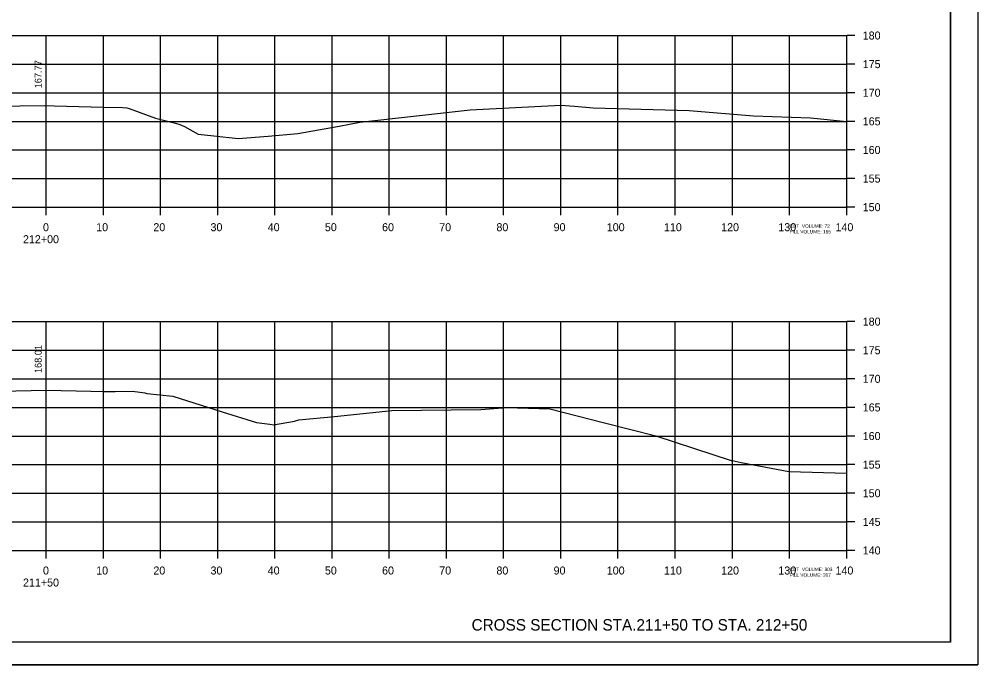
# Model space of a CAD drawing. Extents: x 1368503 to 1373085, y 379840 to 381833.
# Drawn here: x 1368668.3 to 1368836, y 380979.4 to 381092.2 of the extents above; entities that cross this region are included whole.
import ezdxf

# ---------------------------------------------------------------- set-up
doc = ezdxf.new("R2010")
doc.units = 0
for name, color, linetype in [('S_BRIDGE', 7, 'Continuous'), ('S_EDGE_PAVEMENT', 7, 'Continuous'), ('S_MISC_BOUNDARY', 7, 'Continuous'), ('S_PHOTO_CENTERS', 7, 'Continuous'), ('S_PHOTO_NOTES', 7, 'Continuous'), ('S_TRAILS', 7, 'Continuous'), ('S_TRAILS_ANNOT', 7, 'Continuous'), ('S_TREE', 7, 'Continuous')]:
    doc.layers.add(name, color=color, linetype=linetype)

msp = doc.modelspace()

# ---------------------------------------------------------------- linework, layer by layer
at = {"layer": 'S_BRIDGE'}
for q in [(1368831.24, 381188.84), (1368515.06, 380983.38)]:
    msp.add_line((1368831.24, 380983.38), q, dxfattribs=at)
at = {"layer": 'S_EDGE_PAVEMENT'}
for p, q in [((1368813.06, 381059.38), (1368813.06, 381089.38)), ((1368814.46, 381089.38), (1368813.06, 381089.38)), ((1368814.46, 381084.38), (1368813.06, 381084.38)), ((1368814.46, 381079.38), (1368813.06, 381079.38)), ((1368814.46, 381074.38), (1368813.06, 381074.38)), ((1368814.46, 381069.38), (1368813.06, 381069.38)), ((1368814.46, 381064.38), (1368813.06, 381064.38)), ((1368533.06, 381059.38), (1368813.06, 381059.38)), ((1368673.06, 381057.98), (1368673.06, 381059.38)), ((1368683.06, 381057.98), (1368683.06, 381059.38)), ((1368693.06, 381057.98), (1368693.06, 381059.38)), ((1368703.06, 381057.98), (1368703.06, 381059.38)), ((1368713.06, 381057.98), (1368713.06, 381059.38)), ((1368723.06, 381057.98), (1368723.06, 381059.38)), ((1368733.06, 381057.98), (1368733.06, 381059.38)), ((1368743.06, 381057.98), (1368743.06, 381059.38)), ((1368753.06, 381057.98), (1368753.06, 381059.38)), ((1368763.06, 381057.98), (1368763.06, 381059.38)), ((1368773.06, 381057.98), (1368773.06, 381059.38)), ((1368783.06, 381057.98), (1368783.06, 381059.38)), ((1368793.06, 381057.98), (1368793.06, 381059.38)), ((1368803.06, 381057.98), (1368803.06, 381059.38)), ((1368813.06, 381057.98), (1368813.06, 381059.38)), ((1368814.46, 381059.38), (1368813.06, 381059.38)), ((1368813.06, 380999.38), (1368813.06, 381039.38)), ((1368814.46, 381039.38), (1368813.06, 381039.38)), ((1368814.46, 381034.38), (1368813.06, 381034.38)), ((1368814.46, 381029.38), (1368813.06, 381029.38)), ((1368814.46, 381024.38), (1368813.06, 381024.38)), ((1368814.46, 381019.38), (1368813.06, 381019.38)), ((1368814.46, 381014.38), (1368813.06, 381014.38)), ((1368814.46, 381009.38), (1368813.06, 381009.38)), ((1368814.46, 381004.38), (1368813.06, 381004.38)), ((1368533.06, 380999.38), (1368813.06, 380999.38)), ((1368673.06, 380997.98), (1368673.06, 380999.38)), ((1368683.06, 380997.98), (1368683.06, 380999.38)), ((1368693.06, 380997.98), (1368693.06, 380999.38)), ((1368703.06, 380997.98), (1368703.06, 380999.38)), ((1368713.06, 380997.98), (1368713.06, 380999.38)), ((1368723.06, 380997.98), (1368723.06, 380999.38)), ((1368733.06, 380997.98), (1368733.06, 380999.38)), ((1368743.06, 380997.98), (1368743.06, 380999.38)), ((1368753.06, 380997.98), (1368753.06, 380999.38)), ((1368763.06, 380997.98), (1368763.06, 380999.38)), ((1368773.06, 380997.98), (1368773.06, 380999.38)), ((1368783.06, 380997.98), (1368783.06, 380999.38)), ((1368793.06, 380997.98), (1368793.06, 380999.38)), ((1368803.06, 380997.98), (1368803.06, 380999.38)), ((1368813.06, 380997.98), (1368813.06, 380999.38)), ((1368814.46, 380999.38), (1368813.06, 380999.38))]:
    msp.add_line(p, q, dxfattribs=at)
at = {"layer": 'S_MISC_BOUNDARY'}
for points in [[(1368664.16, 381077.03), (1368672.72, 381077.15), (1368674.47, 381077.11), (1368683.1, 381076.88), (1368686.43, 381076.78), (1368687.14, 381076.76), (1368687.55, 381076.61), (1368692.19, 381074.96), (1368695.69, 381074.05), (1368696.45, 381073.8), (1368697.27, 381073.47), (1368699.63, 381072.16), (1368702.36, 381071.86), (1368706.65, 381071.37), (1368711.9, 381071.8), (1368717.09, 381072.24), (1368724.31, 381073.51), (1368727.92, 381074.26), (1368747.18, 381076.42), (1368763.08, 381077.22), (1368765.48, 381077.01), (1368768.72, 381076.74), (1368785.48, 381076.3), (1368796.76, 381075.37), (1368806.73, 381074.98), (1368813.06, 381074.35)], [(1368665.05, 381027.21), (1368673.12, 381027.39), (1368680.85, 381027.2), (1368683.12, 381027.14), (1368685.11, 381027.18), (1368688.17, 381027.2), (1368690.31, 381026.95), (1368690.66, 381026.79), (1368695.19, 381026.32), (1368703.83, 381023.6), (1368709.86, 381021.73), (1368712.19, 381021.44), (1368712.8, 381021.36), (1368716.51, 381021.99), (1368717.25, 381022.19), (1368723.48, 381022.82), (1368733.52, 381023.83), (1368749.06, 381023.99), (1368753.6, 381024.38), (1368761.16, 381024.12), (1368770.48, 381021.75), (1368779.68, 381019.41), (1368792.86, 381015.08), (1368792.87, 381015.08), (1368793.01, 381015.08), (1368794.58, 381014.78), (1368802.94, 381013.19), (1368813.06, 381012.89)]]:
    msp.add_lwpolyline(points, dxfattribs=at)
at = {"layer": 'S_PHOTO_CENTERS'}
for p, q in [((1368533.06, 381089.38), (1368813.06, 381089.38)), ((1368673.06, 381059.38), (1368673.06, 381089.38)), ((1368683.06, 381059.38), (1368683.06, 381089.38)), ((1368693.06, 381059.38), (1368693.06, 381089.38)), ((1368703.06, 381059.38), (1368703.06, 381089.38)), ((1368713.06, 381059.38), (1368713.06, 381089.38)), ((1368723.06, 381059.38), (1368723.06, 381089.38)), ((1368733.06, 381059.38), (1368733.06, 381089.38)), ((1368743.06, 381059.38), (1368743.06, 381089.38)), ((1368753.06, 381059.38), (1368753.06, 381089.38)), ((1368763.06, 381059.38), (1368763.06, 381089.38)), ((1368773.06, 381059.38), (1368773.06, 381089.38)), ((1368783.06, 381059.38), (1368783.06, 381089.38)), ((1368793.06, 381059.38), (1368793.06, 381089.38)), ((1368803.06, 381059.38), (1368803.06, 381089.38)), ((1368813.06, 381059.38), (1368813.06, 381089.38)), ((1368533.06, 381084.38), (1368813.06, 381084.38)), ((1368533.06, 381079.38), (1368813.06, 381079.38)), ((1368533.06, 381074.38), (1368813.06, 381074.38)), ((1368533.06, 381069.38), (1368813.06, 381069.38)), ((1368533.06, 381064.38), (1368813.06, 381064.38)), ((1368533.06, 381059.38), (1368813.06, 381059.38)), ((1368533.06, 381039.38), (1368813.06, 381039.38)), ((1368673.06, 380999.38), (1368673.06, 381039.38)), ((1368683.06, 380999.38), (1368683.06, 381039.38)), ((1368693.06, 380999.38), (1368693.06, 381039.38)), ((1368703.06, 380999.38), (1368703.06, 381039.38)), ((1368713.06, 380999.38), (1368713.06, 381039.38)), ((1368723.06, 380999.38), (1368723.06, 381039.38)), ((1368733.06, 380999.38), (1368733.06, 381039.38)), ((1368743.06, 380999.38), (1368743.06, 381039.38)), ((1368753.06, 380999.38), (1368753.06, 381039.38)), ((1368763.06, 380999.38), (1368763.06, 381039.38)), ((1368773.06, 380999.38), (1368773.06, 381039.38)), ((1368783.06, 380999.38), (1368783.06, 381039.38)), ((1368793.06, 380999.38), (1368793.06, 381039.38)), ((1368803.06, 380999.38), (1368803.06, 381039.38)), ((1368813.06, 380999.38), (1368813.06, 381039.38)), ((1368533.06, 381034.38), (1368813.06, 381034.38)), ((1368533.06, 381029.38), (1368813.06, 381029.38)), ((1368533.06, 381024.38), (1368813.06, 381024.38)), ((1368533.06, 381019.38), (1368813.06, 381019.38)), ((1368533.06, 381014.38), (1368813.06, 381014.38)), ((1368533.06, 381009.38), (1368813.06, 381009.38)), ((1368533.06, 381004.38), (1368813.06, 381004.38)), ((1368533.06, 380999.38), (1368813.06, 380999.38))]:
    msp.add_line(p, q, dxfattribs=at)
at = {"layer": 'S_PHOTO_NOTES'}
msp.add_line((1368502.66, 380979.4), (1368835.99, 380979.4), dxfattribs=at)
for points in [[(1368502.65, 381192.73), (1368835.99, 381192.73), (1368835.99, 380979.4), (1368502.65, 380979.4)], [(1368748.98, 381188.84), (1368748.98, 381178.96), (1368784.71, 381178.96), (1368784.71, 381176.04), (1368807.91, 381176.04), (1368807.91, 381151.71), (1368831.24, 381151.71), (1368831.24, 380983.38), (1368515.06, 380983.38), (1368515.06, 381188.84)]]:
    msp.add_lwpolyline(points, close=True, dxfattribs=at)

# ---------------------------------------------------------------- texts
at = {"layer": 'S_TRAILS'}
for s, height, p in [('180', 1.4, (1368815.86, 381088.68)), ('175', 1.4, (1368815.86, 381083.68)), ('170', 1.4, (1368815.86, 381078.68)), ('165', 1.4, (1368815.86, 381073.68)), ('160', 1.4, (1368815.86, 381068.68)), ('155', 1.4, (1368815.86, 381063.68)), ('150', 1.4, (1368815.86, 381058.68)), ('0', 1.4, (1368672.5, 381055.18)), ('10', 1.4, (1368681.8, 381055.18)), ('20', 1.4, (1368691.8, 381055.18)), ('30', 1.4, (1368701.8, 381055.18)), ('40', 1.4, (1368711.8, 381055.18)), ('50', 1.4, (1368721.8, 381055.18)), ('60', 1.4, (1368731.8, 381055.18)), ('70', 1.4, (1368741.8, 381055.18)), ('80', 1.4, (1368751.8, 381055.18)), ('90', 1.4, (1368761.8, 381055.18)), ('100', 1.4, (1368771.1, 381055.18)), ('110', 1.4, (1368781.1, 381055.18)), ('120', 1.4, (1368791.1, 381055.18)), ('130', 1.4, (1368801.1, 381055.18)), ('CUT  VOLUME: 72', 0.6, (1368803.06, 381055.78)), ('140', 1.4, (1368811.1, 381055.18)), ('212+00', 1.4, (1368669, 381053.08)), ('FILL VOLUME: 165', 0.6, (1368803.06, 381054.78)), ('180', 1.4, (1368815.86, 381038.68)), ('175', 1.4, (1368815.86, 381033.68)), ('170', 1.4, (1368815.86, 381028.68)), ('165', 1.4, (1368815.86, 381023.68)), ('160', 1.4, (1368815.86, 381018.68)), ('155', 1.4, (1368815.86, 381013.68)), ('150', 1.4, (1368815.86, 381008.68)), ('145', 1.4, (1368815.86, 381003.68)), ('140', 1.4, (1368815.86, 380998.68)), ('0', 1.4, (1368672.5, 380995.18)), ('10', 1.4, (1368681.8, 380995.18)), ('20', 1.4, (1368691.8, 380995.18)), ('30', 1.4, (1368701.8, 380995.18)), ('40', 1.4, (1368711.8, 380995.18)), ('50', 1.4, (1368721.8, 380995.18)), ('60', 1.4, (1368731.8, 380995.18)), ('70', 1.4, (1368741.8, 380995.18)), ('80', 1.4, (1368751.8, 380995.18)), ('90', 1.4, (1368761.8, 380995.18)), ('100', 1.4, (1368771.1, 380995.18)), ('110', 1.4, (1368781.1, 380995.18)), ('120', 1.4, (1368791.1, 380995.18)), ('130', 1.4, (1368801.1, 380995.18)), ('CUT  VOLUME: 303', 0.6, (1368803.06, 380995.78)), ('FILL VOLUME: 207', 0.6, (1368803.06, 380994.78)), ('140', 1.4, (1368811.1, 380995.18)), ('211+50', 1.4, (1368669, 380993.08))]:
    msp.add_text(s, height=height, dxfattribs=at).set_placement(p)
at = {"layer": 'S_TRAILS_ANNOT'}
for s, p in [('167.77', (1368672.26, 381080.15)), ('168.01', (1368672.26, 381030.39))]:
    msp.add_text(s, height=1.2, rotation=90, dxfattribs=at).set_placement(p)
at = {"layer": 'S_TREE'}
msp.add_text('CROSS SECTION STA.211+50 TO STA. 212+50', height=2, dxfattribs=at).set_placement((1368747.46, 380985.38))

doc.saveas('drawing.dxf')
